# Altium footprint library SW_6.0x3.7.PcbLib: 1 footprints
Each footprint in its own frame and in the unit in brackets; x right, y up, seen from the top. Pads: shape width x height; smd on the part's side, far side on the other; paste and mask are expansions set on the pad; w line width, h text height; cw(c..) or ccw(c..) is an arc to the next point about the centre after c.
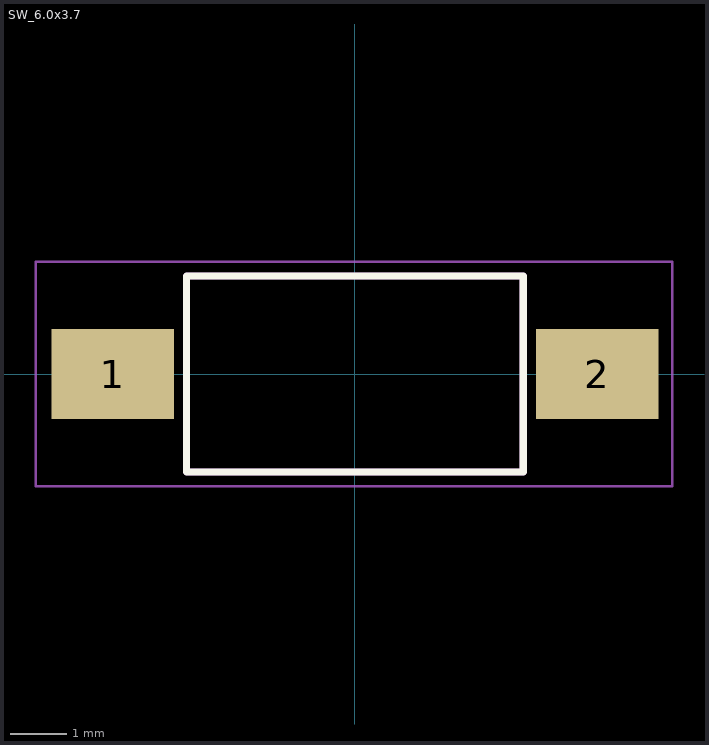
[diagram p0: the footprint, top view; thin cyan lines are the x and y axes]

## SW_6.0x3.7 [mm]
pads (2):
  rect 2.18x1.6 smd: 1(-4.318,0) 2(4.318,0)
Top Overlay:
  lines w0.127: -3,-1.75 -3,1.75 3,1.75 3,-1.75 -3,-1.75
Mechanical 13:
  lines w0.127: -3,-1.75 -3,1.75 3,1.75 3,-1.75 -3,-1.75
Mechanical 15:
  lines w0.05: -5.688,-2 5.654,-2 5.654,2 -5.688,2 -5.688,-2
3D body "SW_6.0x3.7.stp": height 4.37, standoff -0.05, extent -5.018,-1.773 4.951,1.727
